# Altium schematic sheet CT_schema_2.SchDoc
size 176 x 147 mm
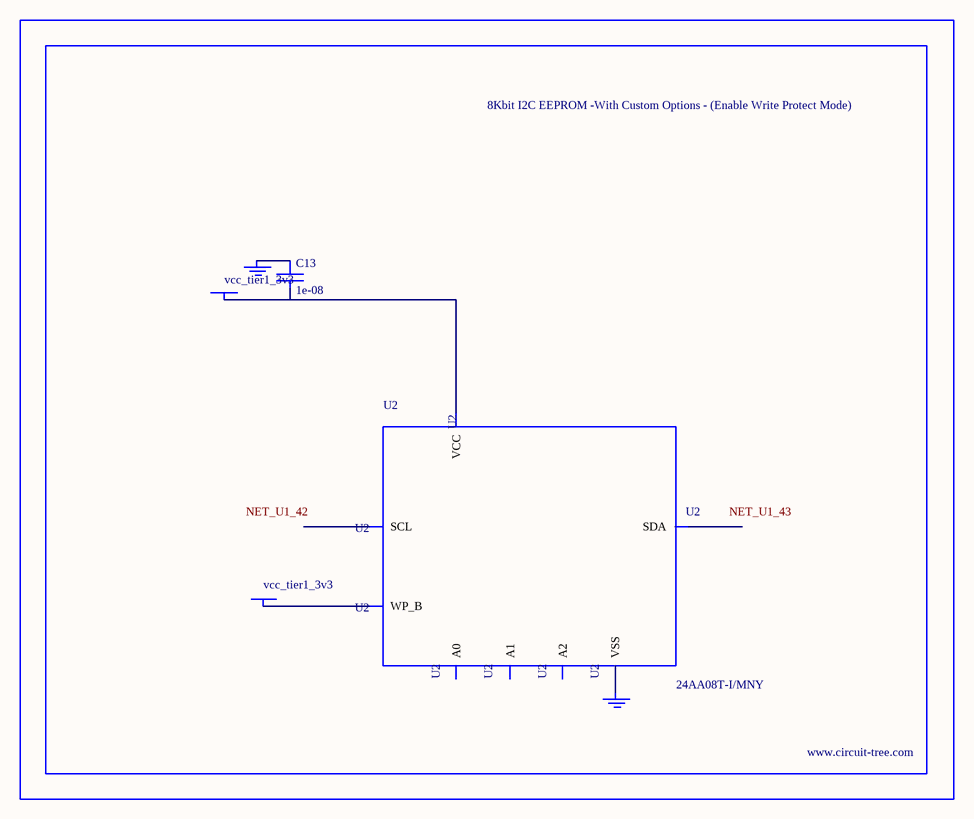
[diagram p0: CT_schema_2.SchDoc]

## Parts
BORDER1  (no value)
C13  1e-08  [C0402]
GND_INSTANCE_1_0  (no value)
GND_INSTANCE_1_1  (no value)
POWER_INSTANCE_1_0  vcc_tier1_3v3
POWER_INSTANCE_1_1  vcc_tier1_3v3
U2  24AA08T-I/MNY  [TDFN-8/6MM]

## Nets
NetC13_1: C13.1 GND_INSTANCE_1_0.0(GND)
NetC13_2: C13.2 POWER_INSTANCE_1_1.0(PWR) U2.8(VCC)
NetGND_INSTANCE_1_1_0: GND_INSTANCE_1_1.0(GND) U2.4(VSS)
NetPOWER_INSTANCE_1_0_0: POWER_INSTANCE_1_0.0(PWR) U2.7(WP_B)

Not connected (* = marked no-connect by the designer): U2 1(A0) 2(A1) 3(A2) 5(SDA) 6(SCL)

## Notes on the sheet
- Labels drawn without touching a wire or pin: NET_U1_42, NET_U1_43

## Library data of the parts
BORDER1 = BORDER_PAGE1
C13 = C0402C103K3RAC
GND_INSTANCE_1_0 GND_INSTANCE_1_1 = GND
POWER_INSTANCE_1_0 POWER_INSTANCE_1_1 = PWR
